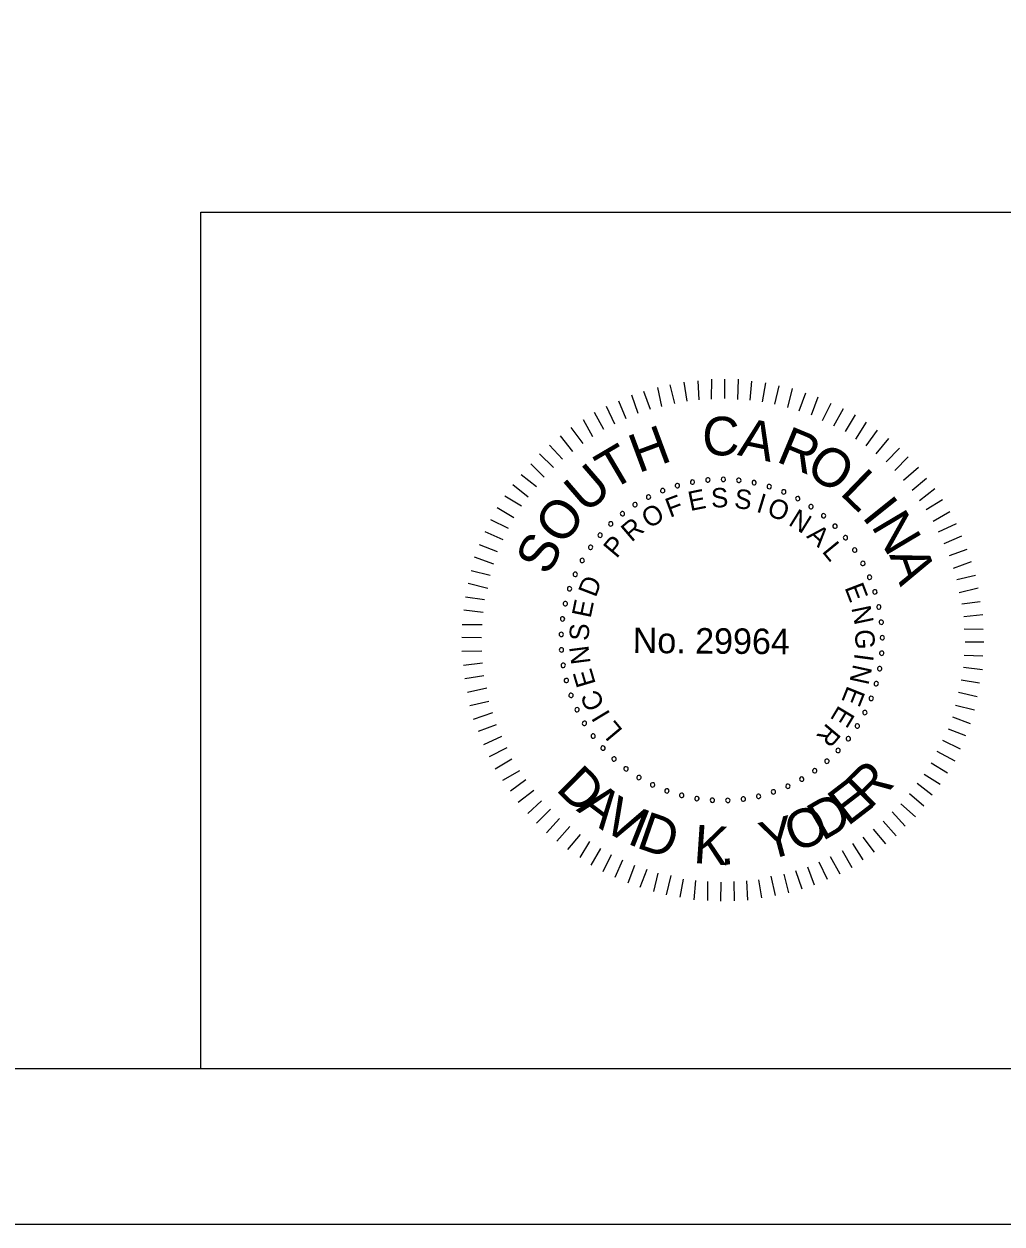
# Model space of a CAD drawing. Extents: x -133.1 to -97, y -1.7 to 20.6.
# Drawn here: x -111.075 to -107.934, y -1.691 to 2.163 of the extents above; entities that cross this region are included whole.
import ezdxf

# ---------------------------------------------------------------- set-up
doc = ezdxf.new("R2010")
doc.units = 0
for name, color, linetype in [('BR_BORDER LINES', 7, 'Continuous'), ('BR_TEXT', 7, 'Continuous'), ('Level 31', 7, 'Continuous')]:
    doc.layers.add(name, color=color, linetype=linetype)

msp = doc.modelspace()

# ---------------------------------------------------------------- linework, layer by layer
at = {"layer": 'BR_BORDER LINES'}
for p, q in [((-110.5071, 1.5591), (-105.1419, 1.5591)), ((-110.5071, -1.191), (-110.5071, 1.5591)), ((-131.3076, -1.191), (-97.6416, -1.191))]:
    msp.add_line(p, q, dxfattribs=at)
at = {"layer": 'BR_TEXT'}
for p, q in [((-108.9849, 0.9447), (-108.999, 1.0041)), ((-108.9454, 0.9521), (-108.9543, 1.0131)), ((-108.9059, 0.9561), (-108.9097, 1.017)), ((-108.8664, 0.9584), (-108.8658, 1.0227)), ((-108.8243, 0.9606), (-108.8238, 1.0224)), ((-108.7823, 0.9577), (-108.78, 1.022)), ((-108.742, 0.9548), (-108.7372, 1.0156)), ((-108.7034, 0.9501), (-108.6926, 1.011)), ((-109.1019, 0.9122), (-109.1229, 0.9708)), ((-109.0623, 0.9248), (-109.0842, 0.9824)), ((-109.0262, 0.9348), (-109.0394, 0.9958)), ((-108.6631, 0.9421), (-108.6489, 1.0012)), ((-108.622, 0.9314), (-108.606, 0.9922)), ((-108.5852, 0.9208), (-108.5633, 0.9781)), ((-108.5458, 0.9076), (-108.5239, 0.9658)), ((-109.1777, 0.8785), (-109.2039, 0.9345)), ((-109.1406, 0.8954), (-109.1642, 0.9514)), ((-108.5099, 0.8902), (-108.482, 0.9457)), ((-108.474, 0.8727), (-108.4427, 0.9282)), ((-109.2475, 0.8371), (-109.278, 0.8914)), ((-109.2122, 0.8608), (-109.2426, 0.9151)), ((-108.4364, 0.8544), (-108.4042, 0.9082)), ((-109.2786, 0.8159), (-109.3177, 0.8668)), ((-108.4031, 0.8301), (-108.3692, 0.8839)), ((-108.3699, 0.8083), (-108.3334, 0.8587)), ((-109.3451, 0.7658), (-109.3868, 0.8107)), ((-109.3123, 0.7904), (-109.3522, 0.8405)), ((-108.3375, 0.7824), (-108.2968, 0.8318)), ((-109.3745, 0.7386), (-109.4188, 0.7827)), ((-108.3059, 0.7572), (-108.2627, 0.8014)), ((-108.2779, 0.7295), (-108.2346, 0.7729)), ((-109.4039, 0.7079), (-109.4474, 0.7503)), ((-108.2498, 0.6984), (-108.2022, 0.74)), ((-109.4291, 0.6763), (-109.4786, 0.7154)), ((-108.2226, 0.6664), (-108.1759, 0.7046)), ((-109.4551, 0.6431), (-109.5046, 0.683)), ((-108.1988, 0.6327), (-108.1496, 0.6718)), ((-109.4768, 0.6141), (-109.5306, 0.6472)), ((-108.1768, 0.6034), (-108.1242, 0.6355)), ((-109.5012, 0.5774), (-109.5549, 0.6096)), ((-108.1548, 0.5663), (-108.1013, 0.5976)), ((-109.5186, 0.5432), (-109.575, 0.5711)), ((-108.137, 0.5318), (-108.0793, 0.5588)), ((-109.5361, 0.5065), (-109.5933, 0.5318)), ((-108.1193, 0.4948), (-108.0624, 0.5192)), ((-109.5536, 0.468), (-109.6117, 0.4899)), ((-108.1025, 0.456), (-108.0456, 0.477)), ((-109.5659, 0.4278), (-109.6275, 0.4506)), ((-108.0891, 0.4156), (-108.0314, 0.4374)), ((-109.5782, 0.3918), (-109.639, 0.4069)), ((-108.079, 0.3794), (-108.0189, 0.3935)), ((-109.5854, 0.3498), (-109.6479, 0.3658)), ((-108.0708, 0.3373), (-108.0106, 0.3522)), ((-109.596, 0.3138), (-109.6569, 0.3221)), ((-108.0625, 0.3012), (-108.0033, 0.3084)), ((-109.6006, 0.2727), (-109.6624, 0.2801)), ((-109.6035, 0.2333), (-109.6679, 0.2338)), ((-108.056, 0.26), (-107.995, 0.2663)), ((-108.0546, 0.2205), (-107.9945, 0.22)), ((-109.6056, 0.1921), (-109.6682, 0.1926)), ((-108.0524, 0.1793), (-107.9915, 0.1788)), ((-109.6042, 0.1492), (-109.6686, 0.148)), ((-108.0553, 0.1364), (-107.9952, 0.1342)), ((-109.602, 0.1105), (-109.6638, 0.1033)), ((-108.0574, 0.0978), (-107.9965, 0.0896)), ((-109.598, 0.0693), (-109.659, 0.0604)), ((-108.0645, 0.0566), (-108.0054, 0.0467)), ((-109.5881, 0.0297), (-109.6508, 0.0165)), ((-108.0735, 0.0172), (-108.0135, 0.003)), ((-109.5815, -0.0124), (-109.6426, -0.0265)), ((-108.0824, -0.0248), (-108.0224, -0.0398)), ((-109.5698, -0.0493), (-109.6318, -0.0703)), ((-108.093, -0.0615), (-108.0357, -0.0835)), ((-109.5582, -0.0881), (-109.6167, -0.1091)), ((-108.107, -0.1001), (-108.0506, -0.122)), ((-109.5413, -0.1251), (-109.599, -0.1521)), ((-108.1245, -0.1368), (-108.0681, -0.1647)), ((-109.5244, -0.1613), (-109.5813, -0.1909)), ((-108.1428, -0.1727), (-108.0856, -0.2032)), ((-109.5076, -0.1984), (-109.5619, -0.2297)), ((-108.1612, -0.2095), (-108.1082, -0.2417)), ((-109.4838, -0.2355), (-109.5382, -0.2668)), ((-109.4626, -0.2648), (-109.5127, -0.3013)), ((-108.1838, -0.2462), (-108.1317, -0.2784)), ((-109.4372, -0.2985), (-109.4873, -0.3376)), ((-108.2063, -0.2752), (-108.1577, -0.3125)), ((-109.4125, -0.3321), (-109.4567, -0.373)), ((-108.2583, -0.3417), (-108.2115, -0.3833)), ((-108.2306, -0.3084), (-108.1846, -0.3483)), ((-109.3836, -0.3582), (-109.4286, -0.4032)), ((-108.2869, -0.3672), (-108.2444, -0.413)), ((-109.3547, -0.3884), (-109.3971, -0.4344)), ((-109.3222, -0.4144), (-109.363, -0.4613)), ((-108.3474, -0.4225), (-108.3075, -0.47)), ((-108.3155, -0.397), (-108.273, -0.4437)), ((-109.289, -0.4404), (-109.3289, -0.4882)), ((-109.2583, -0.4622), (-109.2896, -0.5142)), ((-108.3802, -0.448), (-108.3446, -0.4963)), ((-109.2233, -0.4847), (-109.2546, -0.5386)), ((-108.4475, -0.4911), (-108.4162, -0.5455)), ((-108.4139, -0.4691), (-108.3808, -0.5217)), ((-109.1891, -0.5048), (-109.2162, -0.5603)), ((-109.1523, -0.5222), (-109.1769, -0.5778)), ((-108.5216, -0.5274), (-108.4947, -0.5835)), ((-108.4855, -0.5106), (-108.455, -0.5666)), ((-109.1139, -0.5397), (-109.1358, -0.5962)), ((-109.0745, -0.552), (-109.0973, -0.6102)), ((-109.0386, -0.5644), (-109.0528, -0.6235)), ((-108.9974, -0.5716), (-109.0126, -0.6333)), ((-108.6756, -0.5742), (-108.6624, -0.6361)), ((-108.6344, -0.5677), (-108.6194, -0.627)), ((-108.5974, -0.556), (-108.5764, -0.6145)), ((-108.5578, -0.5443), (-108.5368, -0.6011)), ((-108.9581, -0.5831), (-108.968, -0.6413)), ((-108.9186, -0.5877), (-108.9234, -0.6494)), ((-108.8792, -0.5906), (-108.8797, -0.6524)), ((-108.8372, -0.5935), (-108.8377, -0.6544)), ((-108.7951, -0.5913), (-108.7939, -0.6531)), ((-108.7547, -0.589), (-108.7509, -0.6509)), ((-108.7161, -0.5851), (-108.7062, -0.6435))]:
    msp.add_line(p, q, dxfattribs=at)
for centre, start, end in [((-108.9278, 0.692), 10.6038, 190.6038), ((-108.8784, 0.6987), 5.0653, 185.0653), ((-108.8784, 0.6987), 185.0653, 5.0653), ((-108.8286, 0.7006), 359.5268, 179.5268), ((-108.8286, 0.7006), 179.5268, 359.5268), ((-108.7789, 0.6977), 173.9884, 353.9884), ((-108.7789, 0.6977), 353.9884, 173.9884), ((-108.7296, 0.69), 348.4499, 168.4499), ((-109.0235, 0.6646), 21.6807, 201.6807), ((-109.0235, 0.6646), 201.6807, 21.6807), ((-108.9763, 0.6806), 16.1422, 196.1422), ((-108.9763, 0.6806), 196.1422, 16.1422), ((-108.9278, 0.692), 190.6038, 10.6038), ((-108.7296, 0.69), 168.4499, 348.4499), ((-108.6814, 0.6776), 162.9114, 342.9114), ((-108.6814, 0.6776), 342.9114, 162.9114), ((-108.6345, 0.6606), 157.373, 337.373), ((-108.6345, 0.6606), 337.373, 157.373), ((-109.1121, 0.6192), 32.7576, 212.7576), ((-109.1121, 0.6192), 212.7576, 32.7576), ((-109.0689, 0.644), 27.2191, 207.2191), ((-109.0689, 0.644), 207.2191, 27.2191), ((-108.5896, 0.6391), 151.8345, 331.8345), ((-108.5896, 0.6391), 331.8345, 151.8345), ((-108.5469, 0.6134), 146.2961, 326.2961), ((-108.5469, 0.6134), 326.2961, 146.2961), ((-109.1527, 0.5903), 38.2961, 218.2961), ((-109.1527, 0.5903), 218.2961, 38.2961), ((-108.5069, 0.5837), 140.7576, 320.7576), ((-108.5069, 0.5837), 320.7576, 140.7576), ((-109.1903, 0.5577), 43.8345, 223.8345), ((-109.1903, 0.5577), 223.8345, 43.8345), ((-108.4699, 0.5503), 135.2191, 315.2191), ((-108.4699, 0.5503), 315.2191, 135.2191), ((-109.2246, 0.5215), 49.373, 229.373), ((-109.2246, 0.5215), 229.373, 49.373), ((-108.4363, 0.5134), 129.6807, 309.6807), ((-108.4363, 0.5134), 309.6807, 129.6807), ((-109.2553, 0.4822), 54.9114, 234.9114), ((-109.2553, 0.4822), 234.9114, 54.9114), ((-108.4065, 0.4735), 124.1422, 304.1422), ((-108.4065, 0.4735), 304.1422, 124.1422), ((-109.282, 0.4402), 60.4499, 240.4499), ((-109.282, 0.4402), 240.4499, 60.4499), ((-108.3806, 0.4309), 118.6038, 298.6038), ((-108.3806, 0.4309), 298.6038, 118.6038), ((-109.3045, 0.3957), 65.9884, 245.9884), ((-109.3045, 0.3957), 245.9884, 65.9884), ((-108.359, 0.3861), 113.0653, 293.0653), ((-108.359, 0.3861), 293.0653, 113.0653), ((-109.3227, 0.3493), 71.5268, 251.5268), ((-109.3227, 0.3493), 251.5268, 71.5268), ((-109.3363, 0.3014), 77.0653, 257.0653), ((-108.3418, 0.3393), 107.5268, 287.5268), ((-108.3418, 0.3393), 287.5268, 107.5268), ((-109.3363, 0.3014), 257.0653, 77.0653), ((-108.3292, 0.2911), 101.9884, 281.9884), ((-108.3292, 0.2911), 281.9884, 101.9884), ((-109.3452, 0.2524), 82.6038, 262.6038), ((-109.3452, 0.2524), 262.6038, 82.6038), ((-108.3213, 0.2419), 96.4499, 276.4499), ((-108.3213, 0.2419), 276.4499, 96.4499), ((-109.3493, 0.2027), 88.1422, 268.1422), ((-109.3493, 0.2027), 268.1422, 88.1422), ((-108.3182, 0.1921), 90.9114, 270.9114), ((-108.3182, 0.1921), 270.9114, 90.9114), ((-109.3486, 0.1529), 93.6807, 273.6807), ((-109.3486, 0.1529), 273.6807, 93.6807), ((-108.3199, 0.1423), 85.373, 265.373), ((-108.3199, 0.1423), 265.373, 85.373), ((-109.3431, 0.1033), 99.2191, 279.2191), ((-109.3431, 0.1033), 279.2191, 99.2191), ((-108.3265, 0.0929), 79.8345, 259.8345), ((-108.3265, 0.0929), 259.8345, 79.8345), ((-109.3328, 0.0546), 104.7576, 284.7576), ((-109.3328, 0.0546), 284.7576, 104.7576), ((-108.3377, 0.0444), 74.2961, 254.2961), ((-108.3377, 0.0444), 254.2961, 74.2961), ((-109.3179, 0.007), 110.2961, 290.2961), ((-109.3179, 0.007), 290.2961, 110.2961), ((-108.3536, -0.0028), 68.7576, 248.7576), ((-108.3536, -0.0028), 248.7576, 68.7576), ((-109.2985, -0.0389), 115.8345, 295.8345), ((-109.2985, -0.0389), 295.8345, 115.8345), ((-109.2747, -0.0826), 121.373, 301.373), ((-109.2747, -0.0826), 301.373, 121.373), ((-108.374, -0.0483), 63.2191, 243.2191), ((-108.374, -0.0483), 243.2191, 63.2191), ((-108.3986, -0.0916), 57.6807, 237.6807), ((-108.3986, -0.0916), 237.6807, 57.6807), ((-109.2468, -0.1239), 126.9114, 306.9114), ((-109.2468, -0.1239), 306.9114, 126.9114), ((-108.4273, -0.1323), 52.1422, 232.1422), ((-108.4273, -0.1323), 232.1422, 52.1422), ((-109.2151, -0.1624), 132.4499, 312.4499), ((-109.2151, -0.1624), 312.4499, 132.4499), ((-109.1798, -0.1975), 317.9884, 137.9884), ((-108.4599, -0.1701), 46.6038, 226.6038), ((-108.4599, -0.1701), 226.6038, 46.6038), ((-109.1798, -0.1975), 137.9884, 317.9884), ((-109.1413, -0.2291), 143.5268, 323.5268), ((-109.1413, -0.2291), 323.5268, 143.5268), ((-108.5351, -0.2353), 35.5268, 215.5268), ((-108.4959, -0.2045), 41.0653, 221.0653), ((-108.4959, -0.2045), 221.0653, 41.0653), ((-109.0999, -0.2569), 149.0653, 329.0653), ((-109.0999, -0.2569), 329.0653, 149.0653), ((-108.577, -0.2622), 29.9884, 209.9884), ((-108.577, -0.2622), 209.9884, 29.9884), ((-108.5351, -0.2353), 215.5268, 35.5268), ((-109.056, -0.2805), 154.6038, 334.6038), ((-109.056, -0.2805), 334.6038, 154.6038), ((-109.01, -0.2997), 160.1422, 340.1422), ((-109.01, -0.2997), 340.1422, 160.1422), ((-108.9624, -0.3145), 345.6807, 165.6807), ((-108.6677, -0.3032), 18.9114, 198.9114), ((-108.6677, -0.3032), 198.9114, 18.9114), ((-108.6214, -0.2849), 24.4499, 204.4499), ((-108.6214, -0.2849), 204.4499, 24.4499), ((-108.9624, -0.3145), 165.6807, 345.6807), ((-108.9136, -0.3245), 171.2191, 351.2191), ((-108.9136, -0.3245), 351.2191, 171.2191), ((-108.8641, -0.3299), 356.7576, 176.7576), ((-108.8641, -0.3299), 176.7576, 356.7576), ((-108.8142, -0.3304), 2.2961, 182.2961), ((-108.8142, -0.3304), 182.2961, 2.2961), ((-108.7646, -0.3261), 7.8345, 187.8345), ((-108.7646, -0.3261), 187.8345, 7.8345), ((-108.7156, -0.317), 13.373, 193.373), ((-108.7156, -0.317), 193.373, 13.373)]:
    msp.add_arc(centre, 0.00701, start, end, dxfattribs=at)
at = {"layer": 'Level 31'}
msp.add_lwpolyline([(-133.1409, -1.691), (-97.141, -1.691), (-97.141, 20.309), (-133.1409, 20.309)], close=True, dxfattribs=at)

# ---------------------------------------------------------------- texts
at = {"layer": 'BR_TEXT'}
for s, height, rotation, p in [('C', 0.1241, 359.5482, (-108.8971, 0.7782)), ('A', 0.1241, 348.1981, (-108.7857, 0.779)), ('H', 0.1241, 20.3637, (-109.1015, 0.7199)), ('R', 0.1241, 337.4344, (-108.6624, 0.7591)), ('T', 0.1241, 30.4992, (-109.1894, 0.6624)), ('O', 0.1239, 326.5869, (-108.5702, 0.7224)), ('U', 0.1241, 40.8022, (-109.2706, 0.5876)), ('L', 0.1241, 315.9488, (-108.4576, 0.6546)), ('E', 0.0622, 11.4103, (-108.9351, 0.5987)), ('S', 0.0622, 2.208, (-108.8672, 0.6097)), ('S', 0.0622, 352.6608, (-108.796, 0.6095)), ('O', 0.1241, 52.0267, (-109.3451, 0.4837)), ('F', 0.0622, 20.6127, (-109.0002, 0.577)), ('I', 0.0622, 343.1136, (-108.7257, 0.5975)), ('O', 0.0622, 338.4392, (-108.6923, 0.5873)), ('I', 0.1241, 308.6613, (-108.3862, 0.5803)), ('O', 0.0622, 30.8477, (-109.0676, 0.541)), ('N', 0.0622, 328.2042, (-108.6227, 0.5559)), ('N', 0.1241, 300.7037, (-108.3556, 0.5509)), ('R', 0.0622, 40.3949, (-109.1237, 0.4971)), ('A', 0.0622, 318.657, (-108.5637, 0.5159)), ('S', 0.1239, 63.2511, (-109.3905, 0.3881)), ('P', 0.0622, 49.9421, (-109.1718, 0.4445)), ('L', 0.0622, 309.4546, (-108.5139, 0.4686)), ('A', 0.1241, 289.4792, (-108.2964, 0.4579)), ('D', 0.0622, 69.0364, (-109.2388, 0.3192)), ('E', 0.0622, 291.049, (-108.44, 0.3533)), ('E', 0.0622, 78.2388, (-109.2553, 0.2526)), ('N', 0.0622, 281.8466, (-108.4179, 0.2882)), ('S', 0.0622, 87.786, (-109.2611, 0.1815)), ('No. 29964', 0.08175, 359.5268, (-109.1199, 0.1431)), ('G', 0.0622, 272.2995, (-108.4061, 0.2179)), ('N', 0.0622, 97.3332, (-109.2549, 0.1105)), ('I', 0.0622, 262.4084, (-108.4065, 0.1441)), ('E', 0.0622, 106.5355, (-109.2379, 0.044)), ('N', 0.0622, 257.7339, (-108.411, 0.1095)), ('C', 0.0622, 116.4266, (-109.208, -0.0235)), ('E', 0.0622, 248.1867, (-108.4291, 0.0406)), ('E', 0.0622, 238.9844, (-108.457, -0.0222)), ('I', 0.0622, 121.1011, (-109.1899, -0.0534)), ('L', 0.0622, 129.9595, (-109.1493, -0.1056)), ('R', 0.0622, 229.782, (-108.4947, -0.0797)), ('D', 0.1236, 315.4053, (-109.3698, -0.2962)), ('R', 0.1236, 44.5947, (-108.3589, -0.3617)), ('E', 0.1236, 37.5339, (-108.4295, -0.4156)), ('A', 0.1236, 322.8377, (-109.3032, -0.3618)), ('V', 0.1236, 330.5179, (-109.226, -0.42)), ('D', 0.1236, 30.1015, (-108.5104, -0.4626)), ('I', 0.1236, 338.1981, (-109.1418, -0.4674)), ('D', 0.1236, 340.7995, (-109.1119, -0.4808)), ('Y', 0.1236, 14.8649, (-108.6915, -0.5241)), ('O', 0.1236, 22.4212, (-108.5997, -0.4996)), ('K', 0.1236, 356.098, (-108.9267, -0.5314)), ('.', 0.1236, 3.1588, (-108.838, -0.5377))]:
    msp.add_text(s, height=height, rotation=rotation, dxfattribs=at).set_placement(p)

doc.saveas('drawing.dxf')
